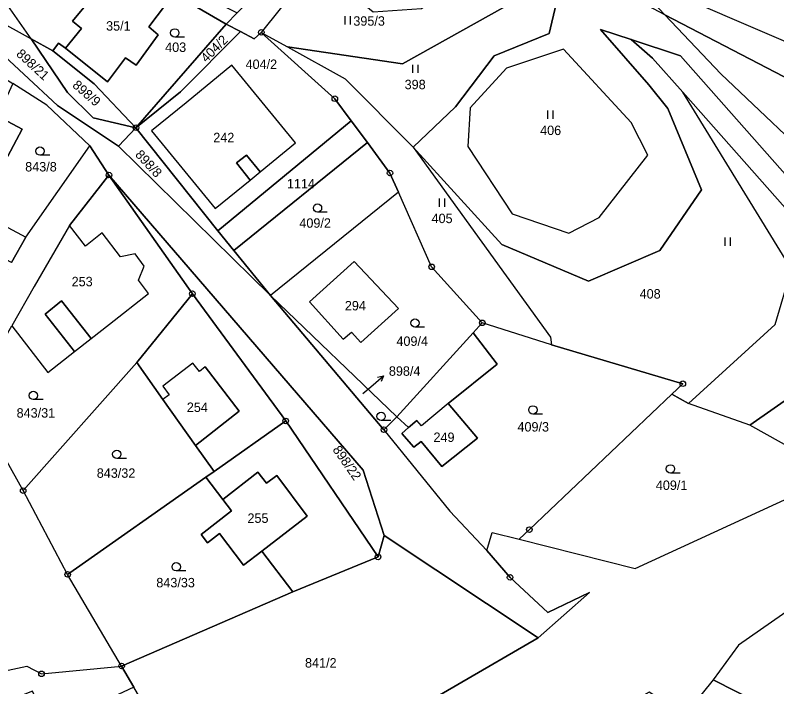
# Model space of a CAD drawing. Extents: x -654083 to -650132, y -1099819 to -1096699.
# Drawn here: x -652332.5 to -652195.2, y -1098329.1 to -1098208 of the extents above; entities that cross this region are included whole.
import ezdxf

# ---------------------------------------------------------------- set-up
doc = ezdxf.new("R2010")
doc.units = 0
for name, color, linetype in [('Geodetické body', 7, 'Continuous'), ('Hranice - vnitř_ kresba', 7, 'Continuous'), ('Obvody jako plochy', 7, 'Continuous'), ('Parcelní čísla', 7, 'Continuous'), ('Prvky pro prodl_ par_ č_', 7, 'Continuous'), ('Značky kultur', 7, 'Continuous')]:
    doc.layers.add(name, color=color, linetype=linetype)

msp = doc.modelspace()

# ---------------------------------------------------------------- linework, layer by layer
at = {"layer": 'Geodetické body'}
for centre, radius in [((-652288.13, -1098211.08), 0.5), ((-652288.13, -1098211.08), 0.001), ((-652274.86, -1098223.05), 0.5), ((-652274.86, -1098223.05), 0.001), ((-652310.73, -1098228.28), 0.5), ((-652310.73, -1098228.28), 0.001), ((-652315.59, -1098236.82), 0.5), ((-652315.59, -1098236.82), 0.001), ((-652264.92, -1098236.45), 0.5), ((-652264.92, -1098236.45), 0.001), ((-652257.41, -1098253.37), 0.5), ((-652257.41, -1098253.37), 0.001), ((-652300.55, -1098258.22), 0.5), ((-652300.55, -1098258.22), 0.001), ((-652248.29, -1098263.48), 0.5), ((-652248.29, -1098263.48), 0.001), ((-652212.12, -1098274.46), 0.5), ((-652212.12, -1098274.46), 0.001), ((-652283.73, -1098281.17), 0.5), ((-652283.73, -1098281.17), 0.001), ((-652266.01, -1098282.75), 0.5), ((-652266.01, -1098282.75), 0.001), ((-652331.06, -1098293.74), 0.5), ((-652331.06, -1098293.74), 0.001), ((-652239.79, -1098300.76), 0.5), ((-652239.79, -1098300.76), 0.001), ((-652267.07, -1098305.69), 0.5), ((-652267.07, -1098305.69), 0.001), ((-652323.04, -1098308.85), 0.5), ((-652323.04, -1098308.85), 0.001), ((-652243.27, -1098309.38), 0.5), ((-652243.27, -1098309.38), 0.001), ((-652313.3, -1098325.37), 0.5), ((-652327.75, -1098326.79), 0.5), ((-652313.3, -1098325.37), 0.001), ((-652327.75, -1098326.79), 0.001)]:
    msp.add_circle(centre, radius, dxfattribs=at)
at = {"layer": 'Hranice - vnitř_ kresba'}
for p, q in [((-652316.52, -1098202.19), (-652322.15, -1098209.05)), ((-652322.15, -1098209.05), (-652320.57, -1098210.39)), ((-652320.57, -1098210.39), (-652323.45, -1098213.94)), ((-652293.43, -1098217), (-652301.67, -1098223.77)), ((-652281.95, -1098231.01), (-652293.43, -1098217)), ((-652301.67, -1098223.77), (-652307.9, -1098228.86)), ((-652307.9, -1098228.86), (-652296.42, -1098242.87)), ((-652288.33, -1098236.24), (-652281.95, -1098231.01)), ((-652290.77, -1098233.26), (-652292.6, -1098234.61)), ((-652288.33, -1098236.24), (-652290.77, -1098233.26)), ((-652292.6, -1098234.61), (-652290.13, -1098237.71)), ((-652290.13, -1098237.71), (-652288.33, -1098236.24)), ((-652296.42, -1098242.87), (-652290.13, -1098237.71)), ((-652324.13, -1098259.48), (-652327.1, -1098261.88)), ((-652318.81, -1098266.32), (-652324.13, -1098259.48)), ((-652327.1, -1098261.88), (-652321.81, -1098268.67)), ((-652300.48, -1098270.72), (-652305.89, -1098274.9)), ((-652299.29, -1098272.22), (-652300.48, -1098270.72)), ((-652298.24, -1098271.41), (-652299.29, -1098272.22)), ((-652298.24, -1098271.41), (-652292.11, -1098279.41)), ((-652305.89, -1098274.9), (-652304.76, -1098276.43)), ((-652304.76, -1098276.43), (-652305.86, -1098277.28)), ((-652254.45, -1098278.04), (-652259.22, -1098282.07)), ((-652292.11, -1098279.41), (-652299.96, -1098285.58)), ((-652261.61, -1098282.36), (-652260.11, -1098281.08)), ((-652259.22, -1098282.07), (-652260.11, -1098281.08)), ((-652295.07, -1098295.34), (-652288.73, -1098290.38)), ((-652288.73, -1098290.38), (-652287.16, -1098292.4)), ((-652287.16, -1098292.4), (-652285.31, -1098290.98)), ((-652285.31, -1098290.98), (-652279.87, -1098298.36)), ((-652279.87, -1098298.36), (-652288.02, -1098304.64))]:
    msp.add_line(p, q, dxfattribs=at)
at = {"layer": 'Obvody jako plochy'}
for points in [[(-652139.42, -1098155.62), (-652150.32, -1098196.47), (-652157.01, -1098225.71), (-652187.94, -1098215.21), (-652210.52, -1098205.53), (-652201.88, -1098186.29), (-652192.91, -1098151.79), (-652181.27, -1098115.57), (-652172.13, -1098115.21), (-652166.56, -1098115.62), (-652165.08, -1098113.69), (-652131.47, -1098125.85)], [(-652292.46, -1098207.53), (-652279.01, -1098193.58), (-652267.89, -1098172.86), (-652266.49, -1098170.41), (-652255.81, -1098151.36), (-652245.17, -1098132.18), (-652241.74, -1098134.1), (-652250.32, -1098149.59), (-652258.8, -1098164.91), (-652267.34, -1098180.33), (-652275.58, -1098195.43), (-652278.33, -1098198.86), (-652288.13, -1098211.08), (-652289.38, -1098212.23), (-652291.9, -1098210.9), (-652294.46, -1098209.58)], [(-652318.44, -1098226.47), (-652310.73, -1098228.28), (-652313.9, -1098231.58), (-652324.89, -1098224.29), (-652343.16, -1098207.33), (-652381.49, -1098186.87), (-652402.05, -1098178.38), (-652412.17, -1098172.97), (-652410.32, -1098170.57), (-652402.11, -1098177.1), (-652387.4, -1098181.49), (-652360.59, -1098195.03), (-652329.61, -1098212.23), (-652323.06, -1098221.92)], [(-652311.94, -1098192.62), (-652304.25, -1098196.97), (-652305.02, -1098198.54), (-652299.61, -1098202.17), (-652297.99, -1098204.75), (-652292.46, -1098207.53), (-652294.46, -1098209.58), (-652303.9, -1098204.05), (-652308.4, -1098210.1), (-652306.7, -1098211.53), (-652310.68, -1098217), (-652312.58, -1098215.65), (-652315.88, -1098220.02), (-652323.45, -1098213.94), (-652324.69, -1098213.02), (-652325.71, -1098214.39), (-652329.61, -1098212.23), (-652334.68, -1098205), (-652332.44, -1098204.6), (-652324.91, -1098196.11), (-652318.47, -1098186.36), (-652312.59, -1098175.4), (-652304.1, -1098180.07)], [(-652259.24, -1098206.82), (-652267.96, -1098207.46), (-652278.33, -1098198.86), (-652288.13, -1098211.08), (-652283.37, -1098213.72), (-652262.67, -1098216.78), (-652233.69, -1098200.51), (-652232.98, -1098198.84), (-652241.54, -1098194.27)], [(-652303.9, -1098204.05), (-652308.4, -1098210.1), (-652306.7, -1098211.53), (-652310.68, -1098217), (-652312.58, -1098215.65), (-652315.88, -1098220.02), (-652323.45, -1098213.94), (-652320.57, -1098210.39), (-652322.15, -1098209.05), (-652316.52, -1098202.19), (-652314.89, -1098203.4), (-652310.86, -1098198.47)], [(-652283.37, -1098213.72), (-652272.98, -1098219.48), (-652260.73, -1098231.76), (-652253.12, -1098224.54), (-652246.13, -1098215.31), (-652236.2, -1098211.27), (-652233.69, -1098200.51), (-652262.67, -1098216.78)], [(-652221.41, -1098212.35), (-652212.54, -1098215.33), (-652190.5, -1098240.25), (-652189.26, -1098238.54), (-652140.51, -1098266.57), (-652137.6, -1098264.99), (-652185.59, -1098237.21), (-652205.26, -1098218.57), (-652215.35, -1098207.89), (-652229.19, -1098200.51), (-652233.69, -1098200.51), (-652236.2, -1098211.27), (-652246.13, -1098215.31), (-652253.12, -1098224.54), (-652260.73, -1098231.76), (-652244.73, -1098249.35), (-652229.13, -1098255.97), (-652216.25, -1098250.45), (-652208.75, -1098239.51), (-652214.85, -1098224.82), (-652218.27, -1098220.54), (-652226.95, -1098210.58)], [(-652294.46, -1098209.58), (-652310.73, -1098228.28), (-652318.23, -1098220.34), (-652325.71, -1098214.39), (-652324.69, -1098213.02), (-652323.45, -1098213.94), (-652315.88, -1098220.02), (-652312.58, -1098215.65), (-652310.68, -1098217), (-652306.7, -1098211.53), (-652308.4, -1098210.1), (-652303.9, -1098204.05)], [(-652119.58, -1098255.21), (-652157.01, -1098225.71), (-652187.94, -1098215.21), (-652210.52, -1098205.53), (-652219.9, -1098203.08), (-652215.35, -1098207.89), (-652121.92, -1098256.48)], [(-652121.92, -1098256.48), (-652215.35, -1098207.89), (-652205.26, -1098218.57), (-652185.59, -1098237.21), (-652137.6, -1098264.99)], [(-652291.9, -1098210.9), (-652302.71, -1098221.81), (-652310.73, -1098228.28), (-652294.46, -1098209.58)], [(-652274.86, -1098223.05), (-652271.91, -1098227.03), (-652295.94, -1098246.88), (-652310.73, -1098228.28), (-652302.71, -1098221.81), (-652291.9, -1098210.9), (-652289.38, -1098212.23), (-652288.13, -1098211.08)], [(-652235.99, -1098266.05), (-652235.79, -1098267.42), (-652248.29, -1098263.48), (-652257.41, -1098253.37), (-652263.37, -1098239.93), (-652264.92, -1098236.45), (-652268.98, -1098230.97), (-652271.91, -1098227.03), (-652274.86, -1098223.05), (-652288.13, -1098211.08), (-652283.37, -1098213.72), (-652272.98, -1098219.48), (-652260.73, -1098231.76)], [(-652214.85, -1098224.82), (-652208.75, -1098239.51), (-652216.25, -1098250.45), (-652229.13, -1098255.97), (-652244.73, -1098249.35), (-652260.73, -1098231.76), (-652235.99, -1098266.05), (-652235.79, -1098267.42), (-652212.12, -1098274.46), (-652214.09, -1098276.33), (-652211.07, -1098278.02), (-652195.49, -1098263.78), (-652192.54, -1098253.81), (-652212.15, -1098221.87), (-652217.6, -1098215.71), (-652221.41, -1098212.35), (-652226.95, -1098210.58), (-652218.27, -1098220.54)], [(-652329.61, -1098212.23), (-652325.71, -1098214.39), (-652318.23, -1098220.34), (-652310.73, -1098228.28), (-652318.44, -1098226.47), (-652323.06, -1098221.92)], [(-652179.91, -1098267.88), (-652162.28, -1098278.39), (-652140.51, -1098266.57), (-652189.26, -1098238.54), (-652190.5, -1098240.25), (-652212.54, -1098215.33), (-652221.41, -1098212.35), (-652217.6, -1098215.71), (-652212.15, -1098221.87), (-652186.77, -1098250.57), (-652185.48, -1098262.61)], [(-652331.24, -1098228.54), (-652334.34, -1098234.45), (-652335.39, -1098236.5), (-652352.08, -1098227.18), (-652344.09, -1098213.5), (-652340.67, -1098215.58), (-652332.9, -1098220.29), (-652335.69, -1098226.19)], [(-652243.9, -1098217.55), (-652250.47, -1098224.68), (-652250.86, -1098231.69), (-652242.89, -1098243.81), (-652232.66, -1098247.28), (-652227.19, -1098244.49), (-652218.46, -1098233.25), (-652221.42, -1098227.35), (-652233.62, -1098214.14)], [(-652242.89, -1098243.81), (-652232.66, -1098247.28), (-652227.19, -1098244.49), (-652218.46, -1098233.25), (-652221.42, -1098227.35), (-652233.62, -1098214.14), (-652243.9, -1098217.55), (-652250.47, -1098224.68), (-652250.86, -1098231.69)], [(-652293.43, -1098217), (-652301.67, -1098223.77), (-652307.9, -1098228.86), (-652296.42, -1098242.87), (-652290.13, -1098237.71), (-652292.6, -1098234.61), (-652290.77, -1098233.26), (-652288.33, -1098236.24), (-652281.95, -1098231.01)], [(-652334.34, -1098234.45), (-652335.39, -1098236.5), (-652352.08, -1098227.18), (-652356.55, -1098233.74), (-652344.54, -1098240.59), (-652330.58, -1098248.02), (-652319.01, -1098231.53), (-652326.79, -1098224.22), (-652332.9, -1098220.29), (-652335.69, -1098226.19), (-652331.24, -1098228.54)], [(-652185.48, -1098262.61), (-652179.91, -1098267.88), (-652200.06, -1098281.92), (-652211.07, -1098278.02), (-652195.49, -1098263.78), (-652192.54, -1098253.81), (-652212.15, -1098221.87), (-652186.77, -1098250.57)], [(-652335.69, -1098226.19), (-652340.03, -1098223.89), (-652343.22, -1098229.73), (-652334.34, -1098234.45), (-652331.24, -1098228.54)], [(-652268.98, -1098230.97), (-652293.06, -1098250.42), (-652295.94, -1098246.88), (-652271.91, -1098227.03)], [(-652310.73, -1098228.28), (-652295.94, -1098246.88), (-652293.06, -1098250.42), (-652286.46, -1098258.54), (-652313.9, -1098231.58)], [(-652264.92, -1098236.45), (-652263.37, -1098239.93), (-652286.46, -1098258.54), (-652293.06, -1098250.42), (-652268.98, -1098230.97)], [(-652337.33, -1098254.19), (-652336.39, -1098252.59), (-652333.9, -1098253.91), (-652340.23, -1098265.14), (-652367.94, -1098249.87), (-652356.55, -1098233.74), (-652344.54, -1098240.59), (-652330.58, -1098248.02), (-652333.17, -1098252.61), (-652343.01, -1098247.41), (-652347.02, -1098245.29), (-652352.6, -1098255.46), (-652342.44, -1098260.99), (-652338.42, -1098253.53)], [(-652321.81, -1098268.67), (-652318.81, -1098266.32), (-652315.52, -1098263.73), (-652308.44, -1098258.18), (-652310.27, -1098255.8), (-652309.22, -1098253.23), (-652310.87, -1098251), (-652313.5, -1098251.55), (-652316.79, -1098247.24), (-652319.82, -1098249.62), (-652322.73, -1098245.89), (-652315.59, -1098236.82), (-652300.55, -1098258.22), (-652310.58, -1098270.64), (-652331.06, -1098293.74), (-652340.51, -1098276.92), (-652333.13, -1098264.04), (-652326.64, -1098272.46)], [(-652265.97, -1098301.83), (-652267.07, -1098305.69), (-652283.73, -1098281.17), (-652300.55, -1098258.22), (-652315.59, -1098236.82), (-652269.73, -1098290.02)], [(-652249.92, -1098265.26), (-652248.29, -1098263.48), (-652257.41, -1098253.37), (-652263.37, -1098239.93), (-652286.46, -1098258.54), (-652263.69, -1098280.44)], [(-652308.44, -1098258.18), (-652310.27, -1098255.8), (-652309.22, -1098253.23), (-652310.87, -1098251), (-652313.5, -1098251.55), (-652316.79, -1098247.24), (-652319.82, -1098249.62), (-652322.73, -1098245.89), (-652329.05, -1098256.91), (-652333.13, -1098264.04), (-652326.64, -1098272.46), (-652321.81, -1098268.67), (-652318.81, -1098266.32), (-652315.52, -1098263.73)], [(-652326.64, -1098272.46), (-652321.81, -1098268.67), (-652327.1, -1098261.88), (-652324.13, -1098259.48), (-652318.81, -1098266.32), (-652315.52, -1098263.73), (-652308.44, -1098258.18), (-652310.27, -1098255.8), (-652309.22, -1098253.23), (-652310.87, -1098251), (-652313.5, -1098251.55), (-652316.79, -1098247.24), (-652319.82, -1098249.62), (-652322.73, -1098245.89), (-652329.05, -1098256.91), (-652333.13, -1098264.04)], [(-652263.38, -1098260.86), (-652271.36, -1098252.39), (-652279.42, -1098259.66), (-652273.35, -1098266.39), (-652271.85, -1098265.17), (-652270.18, -1098267)], [(-652270.18, -1098267), (-652263.38, -1098260.86), (-652271.36, -1098252.39), (-652279.42, -1098259.66), (-652273.35, -1098266.39), (-652271.85, -1098265.17)], [(-652279.42, -1098259.66), (-652273.35, -1098266.39), (-652271.85, -1098265.17), (-652270.18, -1098267), (-652263.38, -1098260.86), (-652271.36, -1098252.39)], [(-652283.73, -1098281.17), (-652296.61, -1098290.28), (-652299.96, -1098285.58), (-652305.86, -1098277.28), (-652310.58, -1098270.64), (-652300.55, -1098258.22)], [(-652286.46, -1098258.54), (-652263.69, -1098280.44), (-652266.01, -1098282.75)], [(-652239.79, -1098300.76), (-652214.09, -1098276.33), (-652212.12, -1098274.46), (-652235.79, -1098267.42), (-652248.29, -1098263.48), (-652249.92, -1098265.26), (-652245.58, -1098270.92), (-652254.45, -1098278.04), (-652249.16, -1098284.28), (-652255.59, -1098289.39), (-652259.32, -1098284.85), (-652260.65, -1098285.91), (-652262.79, -1098283.42), (-652261.61, -1098282.36), (-652263.69, -1098280.44), (-652266.01, -1098282.75), (-652254.16, -1098297.42), (-652247.49, -1098304.55), (-652246.48, -1098301.27), (-652241.65, -1098302.5)], [(-652255.59, -1098289.39), (-652249.16, -1098284.28), (-652254.45, -1098278.04), (-652245.58, -1098270.92), (-652249.92, -1098265.26), (-652263.69, -1098280.44), (-652261.61, -1098282.36), (-652262.79, -1098283.42), (-652260.65, -1098285.91), (-652259.32, -1098284.85)], [(-652299.96, -1098285.58), (-652296.61, -1098290.28), (-652298.11, -1098291.33), (-652323.04, -1098308.85), (-652331.06, -1098293.74), (-652310.58, -1098270.64), (-652305.86, -1098277.28)], [(-652304.76, -1098276.43), (-652305.86, -1098277.28), (-652299.96, -1098285.58), (-652292.11, -1098279.41), (-652298.24, -1098271.41), (-652299.29, -1098272.22), (-652300.48, -1098270.72), (-652305.89, -1098274.9)], [(-652313.3, -1098325.37), (-652323.04, -1098308.85), (-652331.06, -1098293.74), (-652340.51, -1098276.92), (-652362.69, -1098315.92), (-652340.76, -1098328.13), (-652338.05, -1098327), (-652330.4, -1098325.42), (-652327.75, -1098326.79)], [(-652220.74, -1098307.8), (-652183.99, -1098290.88), (-652200.06, -1098281.92), (-652211.07, -1098278.02), (-652214.09, -1098276.33), (-652239.79, -1098300.76), (-652241.65, -1098302.5)], [(-652259.32, -1098284.85), (-652255.59, -1098289.39), (-652249.16, -1098284.28), (-652254.45, -1098278.04), (-652259.22, -1098282.07), (-652260.11, -1098281.08), (-652261.61, -1098282.36), (-652262.79, -1098283.42), (-652260.65, -1098285.91)], [(-652283.73, -1098281.17), (-652267.07, -1098305.69), (-652282.43, -1098312.02), (-652288.02, -1098304.64), (-652291.32, -1098307.18), (-652295.68, -1098301.47), (-652297.84, -1098303.13), (-652298.96, -1098301.66), (-652293.52, -1098297.39), (-652295.07, -1098295.34), (-652298.11, -1098291.33), (-652296.61, -1098290.28)], [(-652298.96, -1098301.66), (-652297.84, -1098303.13), (-652295.68, -1098301.47), (-652291.32, -1098307.18), (-652288.02, -1098304.64), (-652279.87, -1098298.36), (-652285.31, -1098290.98), (-652287.16, -1098292.4), (-652288.73, -1098290.38), (-652295.07, -1098295.34), (-652293.52, -1098297.39)], [(-652297.84, -1098303.13), (-652295.68, -1098301.47), (-652291.32, -1098307.18), (-652288.02, -1098304.64), (-652282.43, -1098312.02), (-652313.3, -1098325.37), (-652323.04, -1098308.85), (-652298.11, -1098291.33), (-652295.07, -1098295.34), (-652293.52, -1098297.39), (-652298.96, -1098301.66)], [(-652238.2, -1098320.29), (-652267.15, -1098337.1), (-652297.55, -1098352.57), (-652311.1, -1098329.18), (-652313.3, -1098325.37), (-652282.43, -1098312.02), (-652267.07, -1098305.69), (-652265.97, -1098301.83)], [(-652181.03, -1098342.49), (-652170.94, -1098327.01), (-652158.52, -1098336.49), (-652150.85, -1098325.58), (-652176.99, -1098308.27), (-652186.79, -1098310.96), (-652202.08, -1098321.61), (-652206.66, -1098327.84), (-652189.68, -1098336.44)], [(-652338.05, -1098327), (-652330.4, -1098325.42), (-652327.75, -1098326.79), (-652313.3, -1098325.37), (-652311.1, -1098329.18), (-652326.52, -1098336.41), (-652329.39, -1098329.93), (-652391.55, -1098354.62), (-652381.5, -1098366.27), (-652399.95, -1098365.36), (-652478.52, -1098362.63), (-652531.67, -1098372.21), (-652535.49, -1098366.17), (-652545.7, -1098345.51), (-652546.92, -1098343), (-652518.45, -1098354.28), (-652508.1, -1098348.73), (-652482.03, -1098339.62), (-652463.05, -1098328.79), (-652450.84, -1098332.97), (-652422.5, -1098351.89), (-652404.15, -1098351.55), (-652393.84, -1098350.3), (-652340.76, -1098328.13)], [(-652123.82, -1098393.2), (-652119.38, -1098407.08), (-652111.42, -1098409.61), (-652113.89, -1098393.93), (-652108.27, -1098386.27), (-652112.93, -1098384.7), (-652118.58, -1098384.7), (-652134.86, -1098374.22), (-652138.7, -1098371.78), (-652155.4, -1098360.1), (-652160.37, -1098356.72), (-652181.03, -1098342.49), (-652189.68, -1098336.44), (-652206.66, -1098327.84), (-652210.39, -1098332.49), (-652198.54, -1098339.93), (-652183.96, -1098350.25), (-652159.34, -1098367.48), (-652138.48, -1098380.69)]]:
    msp.add_lwpolyline(points, close=True, dxfattribs=at)
for points in [[(-652360.59, -1098195.03), (-652329.61, -1098212.23), (-652334.68, -1098205)], [(-652343.16, -1098207.33), (-652324.89, -1098224.29), (-652313.9, -1098231.58), (-652286.46, -1098258.54), (-652266.01, -1098282.75), (-652254.16, -1098297.42), (-652247.49, -1098304.55), (-652243.27, -1098309.38), (-652236.44, -1098315.73), (-652228.97, -1098312.1), (-652238.2, -1098320.29), (-652265.97, -1098301.83), (-652269.73, -1098290.02), (-652315.59, -1098236.82), (-652319.01, -1098231.53), (-652326.79, -1098224.22), (-652332.9, -1098220.29)], [(-652246.48, -1098301.27), (-652241.65, -1098302.5), (-652220.74, -1098307.8), (-652183.99, -1098290.88), (-652200.06, -1098281.92), (-652179.91, -1098267.88), (-652162.28, -1098278.39), (-652140.51, -1098266.57), (-652137.6, -1098264.99), (-652121.92, -1098256.48), (-652119.58, -1098255.21), (-652103.46, -1098246.87), (-652084.53, -1098241.97), (-652067.72, -1098237.6), (-652064.28, -1098217.22), (-652064.08, -1098215.97), (-652052.14, -1098228.35)], [(-652333.17, -1098252.61), (-652330.58, -1098248.02), (-652319.01, -1098231.53), (-652315.59, -1098236.82), (-652322.73, -1098245.89), (-652329.05, -1098256.91), (-652333.13, -1098264.04)], [(-652729.64, -1098315.8), (-652661.4, -1098344.97), (-652637.26, -1098355.21), (-652619.41, -1098357.13), (-652535.49, -1098366.17), (-652531.67, -1098372.21), (-652478.52, -1098362.63), (-652399.95, -1098365.36), (-652381.5, -1098366.27), (-652356.63, -1098362.42), (-652336.38, -1098361.13), (-652302.52, -1098355.1), (-652297.55, -1098352.57), (-652267.15, -1098337.1), (-652238.2, -1098320.29), (-652228.97, -1098312.1), (-652236.44, -1098315.73), (-652243.27, -1098309.38), (-652247.49, -1098304.55), (-652246.48, -1098301.27)], [(-652186.79, -1098310.96), (-652202.08, -1098321.61), (-652206.66, -1098327.84), (-652210.39, -1098332.49), (-652211.78, -1098334.22), (-652218.22, -1098330.08), (-652253.24, -1098349.9), (-652272.67, -1098357.52), (-652318, -1098374.7), (-652321.64, -1098375.04), (-652359.97, -1098376.98), (-652389.22, -1098379.47), (-652402.32, -1098381.08), (-652418.27, -1098386.43), (-652418.63, -1098382.46), (-652433.19, -1098384.93), (-652445.3, -1098386.68), (-652445.4, -1098388.53), (-652462.43, -1098389.36)]]:
    msp.add_lwpolyline(points, dxfattribs=at)
at = {"layer": 'Prvky pro prodl_ par_ č_'}
for p, q in [((-652268.38, -1098274.99), (-652266.12, -1098273.02)), ((-652269.8, -1098276.23), (-652268.38, -1098274.99))]:
    msp.add_line(p, q, dxfattribs=at)
msp.add_lwpolyline([(-652267.2, -1098273.3), (-652266.12, -1098273.02), (-652266.54, -1098274.05)], dxfattribs=at)
at = {"layer": 'Značky kultur'}
for p, q in [((-652273.05, -1098208.15), (-652273.05, -1098209.65)), ((-652272.03, -1098209.65), (-652272.03, -1098208.15)), ((-652301.98, -1098211.93), (-652303.73, -1098211.93)), ((-652260.87, -1098216.91), (-652260.87, -1098218.41)), ((-652259.84, -1098218.41), (-652259.84, -1098216.91)), ((-652236.52, -1098225.17), (-652236.52, -1098226.67)), ((-652235.49, -1098226.67), (-652235.49, -1098225.17)), ((-652326.28, -1098233.24), (-652328.03, -1098233.24)), ((-652256.06, -1098241.05), (-652256.06, -1098242.55)), ((-652255.04, -1098242.55), (-652255.04, -1098241.05)), ((-652276.24, -1098243.52), (-652277.99, -1098243.52)), ((-652204.57, -1098248.1), (-652204.57, -1098249.6)), ((-652203.55, -1098249.6), (-652203.55, -1098248.1)), ((-652258.67, -1098264.26), (-652260.42, -1098264.26)), ((-652327.48, -1098277.31), (-652329.23, -1098277.31)), ((-652264.78, -1098281.09), (-652266.53, -1098281.09)), ((-652237.41, -1098279.92), (-652239.16, -1098279.92)), ((-652312.43, -1098287.93), (-652314.18, -1098287.93)), ((-652212.61, -1098290.56), (-652214.36, -1098290.56)), ((-652301.72, -1098308.22), (-652303.47, -1098308.22))]:
    msp.add_line(p, q, dxfattribs=at)
for centre in [(-652303.73, -1098211.18), (-652328.03, -1098232.49), (-652277.99, -1098242.77), (-652260.42, -1098263.51), (-652329.23, -1098276.56), (-652266.53, -1098280.34), (-652239.16, -1098279.17), (-652314.18, -1098287.18), (-652214.36, -1098289.81), (-652303.47, -1098307.47)]:
    msp.add_circle(centre, 0.75, dxfattribs=at)

# ---------------------------------------------------------------- texts
at = {"layer": 'Parcelní čísla'}
for s, height, p in [('395/3', 1.7, (-652271.53, -1098209.88)), ('35/1', 1.7, (-652316.11, -1098210.77)), ('403', 1.7, (-652305.46, -1098214.61)), ('398', 1.7, (-652262.28, -1098221.34)), ('406', 1.7, (-652237.85, -1098229.6)), ('242', 1.7, (-652296.78, -1098230.9)), ('843/8', 1.7, (-652330.69, -1098236.17)), ('1114', 1.7, (-652283.51, -1098239.23)), ('405', 1.7, (-652257.43, -1098245.49)), ('409/2', 1.7, (-652281.26, -1098246.32)), ('253', 1.7, (-652322.32, -1098256.88)), ('408', 1.7, (-652219.91, -1098259.09)), ('294', 1.7, (-652273.06, -1098261.23)), ('409/4', 1.7, (-652263.76, -1098267.63)), ('898/4', 0.1, (-652269.98, -1098276.23)), ('254', 1.7, (-652301.55, -1098279.55)), ('843/31', 1.7, (-652332.24, -1098280.57)), ('409/3', 1.7, (-652241.94, -1098283.08)), ('249', 1.7, (-652257.08, -1098284.96)), ('843/32', 1.7, (-652317.79, -1098291.42)), ('409/1', 1.7, (-652216.99, -1098293.61)), ('255', 1.7, (-652290.62, -1098299.55)), ('843/33', 1.7, (-652307.05, -1098311.18)), ('841/2', 1.7, (-652280.24, -1098325.65))]:
    msp.add_text(s, height=height, dxfattribs=at).set_placement(p)
for s, rotation, p in [('404/2', 44.901, (-652298.02, -1098216.63)), ('898/21', 317.34, (-652332.44, -1098215.15)), ('898/9', 318.897, (-652322.31, -1098220.82)), ('898/8', 312.84, (-652310.98, -1098233.24)), ('898/22', 304.974, (-652275.35, -1098286.36))]:
    msp.add_text(s, height=1.7, rotation=rotation, dxfattribs=at).set_placement(p)
at = {"layer": 'Prvky pro prodl_ par_ č_'}
for s, p in [('404/2', (-652290.96, -1098217.68)), ('898/4', (-652265.12, -1098273.02))]:
    msp.add_text(s, height=1.7, dxfattribs=at).set_placement(p)

doc.saveas('drawing.dxf')
